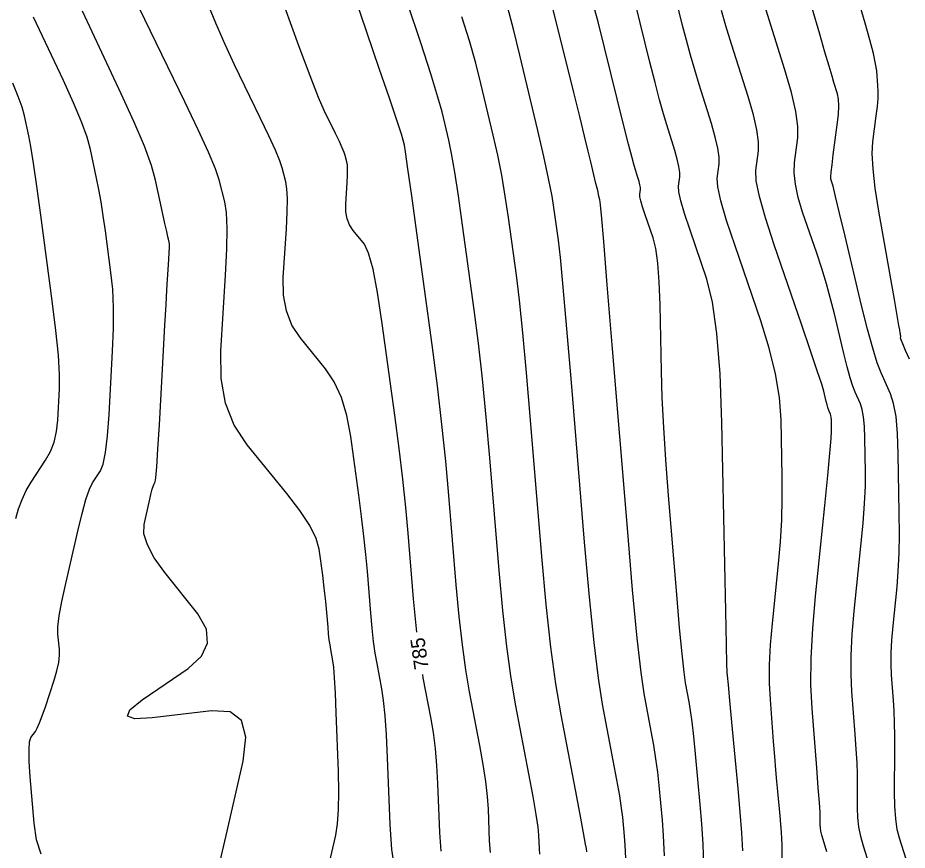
# Model space of a CAD drawing. Extents: x 2082232 to 2083549, y 592624 to 593832.
# Drawn here: x 2082528.23 to 2082571.85, y 593085.62 to 593126.44 of the extents above; entities that cross this region are included whole.
import ezdxf

# ---------------------------------------------------------------- set-up
doc = ezdxf.new("R2010")
doc.units = 0
doc.layers.add('DT_X_Contour_Major', color=7, linetype='Continuous')
doc.layers.add('DT_X_Contour_Minor', color=7, linetype='Continuous')

msp = doc.modelspace()

# ---------------------------------------------------------------- linework, layer by layer
at = {"layer": 'DT_X_Contour_Major'}
for points in [[(2082559.944, 593085.357), (2082559.9, 593086.34), (2082559.845, 593087.094), (2082559.682, 593088.8), (2082559.612, 593089.447), (2082559.525, 593090.106), (2082559.419, 593090.778), (2082559.296, 593091.463), (2082558.943, 593093.306), (2082558.793, 593094.331), (2082558.606, 593096.026), (2082558.383, 593098.389), (2082558.124, 593101.422), (2082557.384, 593110.401), (2082557.14, 593113.354), (2082556.964, 593115.481), (2082556.855, 593116.78), (2082556.813, 593117.253), (2082556.791, 593117.411), (2082556.772, 593117.512), (2082556.732, 593117.699), (2082556.669, 593117.969), (2082556.585, 593118.325), (2082556.332, 593119.385), (2082556.209, 593119.895), (2082556.028, 593120.632), (2082555.792, 593121.595), (2082555.498, 593122.784), (2082554.64, 593126.255), (2082554.344, 593127.414)], [(2082570.117, 593084.525), (2082569.708, 593085.822), (2082569.574, 593086.303), (2082569.479, 593086.772), (2082569.423, 593087.231), (2082569.407, 593087.68), (2082569.414, 593088.861), (2082569.408, 593089.346), (2082569.387, 593089.917), (2082569.349, 593090.572), (2082569.295, 593091.313), (2082569.13, 593093.402), (2082569.091, 593094.237), (2082569.099, 593095.173), (2082569.152, 593096.212), (2082569.251, 593097.353), (2082569.577, 593100.533), (2082569.682, 593101.654), (2082569.755, 593102.633), (2082569.794, 593103.469), (2082569.8, 593104.163), (2082569.773, 593105.824), (2082569.751, 593106.396), (2082569.707, 593106.868), (2082569.642, 593107.238), (2082569.554, 593107.507), (2082569.289, 593108.091), (2082569.181, 593108.374), (2082569.054, 593108.784), (2082568.908, 593109.322), (2082568.743, 593109.987), (2082568.278, 593111.931), (2082568.093, 593112.664), (2082567.887, 593113.403), (2082567.66, 593114.148), (2082567.411, 593114.901), (2082566.719, 593116.916), (2082566.5, 593117.635), (2082566.361, 593118.278), (2082566.302, 593118.846), (2082566.323, 593119.34), (2082566.485, 593120.555), (2082566.491, 593121.106), (2082566.386, 593121.846), (2082566.171, 593122.776), (2082565.845, 593123.896), (2082564.829, 593127.135)], [(2082547.797, 593096.318), (2082547.743, 593096.803), (2082547.639, 593097.948), (2082547.374, 593101.163), (2082547.258, 593102.429), (2082547.11, 593103.816), (2082546.929, 593105.324), (2082546.715, 593106.952), (2082546.101, 593111.457), (2082545.874, 593112.967), (2082545.652, 593114.117), (2082545.437, 593114.909), (2082545.228, 593115.341), (2082544.678, 593116.015), (2082544.5, 593116.286), (2082544.381, 593116.592), (2082544.319, 593116.933), (2082544.315, 593117.31), (2082544.381, 593118.363), (2082544.399, 593118.722), (2082544.404, 593119.011), (2082544.394, 593119.231), (2082544.371, 593119.38), (2082544.291, 593119.683), (2082544.239, 593119.836), (2082544.142, 593120.068), (2082544.001, 593120.377), (2082543.816, 593120.765), (2082543.261, 593121.904), (2082542.984, 593122.541), (2082542.57, 593123.595), (2082542.017, 593125.067), (2082541.327, 593126.957)], [(2082528.135, 593101.887), (2082528.267, 593102.369), (2082528.437, 593102.829), (2082528.645, 593103.266), (2082528.891, 593103.679), (2082529.597, 593104.75), (2082529.833, 593105.173), (2082530.011, 593105.641), (2082530.13, 593106.153), (2082530.192, 593106.709), (2082530.278, 593108.252), (2082530.28, 593108.955), (2082530.221, 593109.907), (2082530.101, 593111.109), (2082529.92, 593112.561), (2082529.357, 593116.764), (2082529.162, 593118.189), (2082529, 593119.312), (2082528.871, 593120.132), (2082528.775, 593120.651), (2082528.564, 593121.631), (2082528.446, 593122.055), (2082528.252, 593122.591), (2082527.982, 593123.241)], [(2082548.998, 593085.579), (2082548.927, 593086.491), (2082548.834, 593088.893), (2082548.786, 593089.771), (2082548.712, 593090.607), (2082548.612, 593091.399), (2082548.486, 593092.147), (2082548.116, 593094.084), (2082548.089, 593094.239)]]:
    msp.add_lwpolyline(points, dxfattribs=at)
at = {"layer": 'DT_X_Contour_Minor'}
for points in [[(2082571.964, 593109.701), (2082571.77, 593110.133), (2082571.632, 593110.45), (2082571.55, 593110.65), (2082571.523, 593110.734), (2082571.527, 593110.805), (2082571.527, 593110.836), (2082571.524, 593110.876), (2082571.517, 593110.925), (2082571.508, 593110.982), (2082571.478, 593111.148), (2082571.442, 593111.354), (2082571.355, 593111.85), (2082571.217, 593112.635), (2082570.46, 593116.962), (2082570.281, 593118.088), (2082570.171, 593119.03), (2082570.131, 593119.786), (2082570.161, 593120.358), (2082570.331, 593121.634), (2082570.384, 593122.087), (2082570.416, 593122.487), (2082570.425, 593122.834), (2082570.413, 593123.129), (2082570.353, 593123.846), (2082570.3, 593124.193), (2082570.188, 593124.699), (2082570.016, 593125.362), (2082569.784, 593126.184), (2082569.086, 593128.585)], [(2082551.414, 593085.506), (2082551.369, 593086.091), (2082551.309, 593087.631), (2082551.266, 593088.26), (2082551.181, 593088.992), (2082551.055, 593089.825), (2082550.887, 593090.761), (2082550.384, 593093.393), (2082550.202, 593094.462), (2082550.033, 593095.693), (2082549.878, 593097.087), (2082549.736, 593098.643), (2082549.376, 593103.01), (2082549.223, 593104.701), (2082549.033, 593106.497), (2082548.807, 593108.399), (2082548.544, 593110.406), (2082547.796, 593115.9), (2082547.547, 593117.714), (2082547.363, 593119.036), (2082547.244, 593119.866), (2082547.19, 593120.203), (2082547.132, 593120.447), (2082547.042, 593120.736), (2082546.817, 593121.418), (2082546.456, 593122.494), (2082545.96, 593123.964), (2082544.456, 593128.41)], [(2082565.716, 593085.235), (2082565.71, 593085.905), (2082565.703, 593086.181), (2082565.685, 593086.507), (2082565.657, 593086.882), (2082565.62, 593087.307), (2082565.505, 593088.505), (2082565.46, 593088.994), (2082565.411, 593089.565), (2082565.357, 593090.216), (2082565.298, 593090.948), (2082565.135, 593093.008), (2082565.096, 593093.821), (2082565.1, 593094.715), (2082565.147, 593095.688), (2082565.238, 593096.743), (2082565.537, 593099.661), (2082565.632, 593100.749), (2082565.694, 593101.826), (2082565.722, 593102.89), (2082565.717, 593103.941), (2082565.658, 593106.73), (2082565.58, 593107.818), (2082565.388, 593108.989), (2082565.084, 593110.245), (2082564.667, 593111.584), (2082563.403, 593115.267), (2082562.992, 593116.509), (2082562.71, 593117.473), (2082562.555, 593118.16), (2082562.527, 593118.568), (2082562.623, 593119.285), (2082562.626, 593119.61), (2082562.564, 593120.047), (2082562.437, 593120.596), (2082562.245, 593121.257), (2082561.645, 593123.169), (2082561.426, 593123.888), (2082561.217, 593124.611), (2082561.02, 593125.339), (2082560.833, 593126.07), (2082560.35, 593128.026)], [(2082571.789, 593085.189), (2082571.466, 593086.215), (2082571.36, 593086.646), (2082571.286, 593087.17), (2082571.243, 593087.786), (2082571.232, 593088.494), (2082571.244, 593090.506), (2082571.243, 593091.226), (2082571.232, 593091.875), (2082571.21, 593092.455), (2082571.178, 593092.964), (2082571.078, 593094.228), (2082571.055, 593094.733), (2082571.059, 593095.3), (2082571.091, 593095.929), (2082571.151, 593096.62), (2082571.348, 593098.544), (2082571.411, 593099.311), (2082571.45, 593100.17), (2082571.467, 593101.121), (2082571.46, 593102.164), (2082571.411, 593105.065), (2082571.374, 593106.066), (2082571.298, 593106.889), (2082571.183, 593107.536), (2082571.029, 593108.007), (2082570.567, 593109.028), (2082570.378, 593109.522), (2082570.155, 593110.238), (2082569.9, 593111.178), (2082569.612, 593112.34), (2082568.8, 593115.737), (2082568.532, 593116.857), (2082568.335, 593117.673), (2082568.21, 593118.183), (2082568.156, 593118.387), (2082568.109, 593118.524), (2082568.103, 593118.638), (2082568.119, 593118.876), (2082568.159, 593119.239), (2082568.221, 593119.725), (2082568.417, 593121.19), (2082568.473, 593121.697), (2082568.494, 593122.119), (2082568.48, 593122.457), (2082568.431, 593122.711), (2082568.254, 593123.275), (2082568.161, 593123.58), (2082568.014, 593124.075), (2082567.814, 593124.759), (2082567.559, 593125.632), (2082566.809, 593128.213)], [(2082543.529, 593085.083), (2082543.821, 593086.365), (2082543.912, 593086.92), (2082543.965, 593087.625), (2082543.98, 593088.478), (2082543.958, 593089.481), (2082543.846, 593092.353), (2082543.805, 593093.322), (2082543.764, 593094.072), (2082543.724, 593094.604), (2082543.685, 593094.919), (2082543.58, 593095.467), (2082543.542, 593095.689), (2082543.507, 593095.945), (2082543.475, 593096.235), (2082543.445, 593096.559), (2082543.37, 593097.468), (2082543.337, 593097.826), (2082543.295, 593098.218), (2082543.244, 593098.644), (2082543.184, 593099.105), (2082543.01, 593100.379), (2082542.862, 593100.908), (2082542.547, 593101.542), (2082542.067, 593102.281), (2082541.42, 593103.123), (2082539.474, 593105.509), (2082538.846, 593106.466), (2082538.423, 593107.549), (2082538.204, 593108.758), (2082538.19, 593110.092), (2082538.424, 593113.817), (2082538.488, 593115.089), (2082538.503, 593116.113), (2082538.47, 593116.889), (2082538.388, 593117.416), (2082538.106, 593118.491), (2082537.921, 593119.032), (2082537.579, 593119.851), (2082537.08, 593120.947), (2082536.422, 593122.32), (2082534.46, 593126.351), (2082533.802, 593127.711)], [(2082546.776, 593084.385), (2082546.581, 593085.652), (2082546.484, 593086.891), (2082546.358, 593090.154), (2082546.306, 593091.283), (2082546.243, 593092.222), (2082546.169, 593092.972), (2082546.085, 593093.533), (2082545.848, 593094.775), (2082545.762, 593095.28), (2082545.682, 593095.861), (2082545.609, 593096.519), (2082545.542, 593097.254), (2082545.372, 593099.315), (2082545.298, 593100.127), (2082545.203, 593101.017), (2082545.087, 593101.984), (2082544.949, 593103.029), (2082544.555, 593105.918), (2082544.368, 593106.937), (2082544.1, 593107.83), (2082543.752, 593108.595), (2082543.324, 593109.232), (2082542.076, 593110.762), (2082541.673, 593111.376), (2082541.402, 593112.07), (2082541.261, 593112.845), (2082541.252, 593113.701), (2082541.403, 593116.09), (2082541.444, 593116.906), (2082541.453, 593117.562), (2082541.432, 593118.06), (2082541.38, 593118.398), (2082541.199, 593119.087), (2082541.08, 593119.434), (2082540.861, 593119.959), (2082540.54, 593120.662), (2082540.119, 593121.543), (2082538.86, 593124.128), (2082538.393, 593125.126), (2082537.936, 593126.181), (2082537.488, 593127.293)], [(2082553.831, 593085.433), (2082553.811, 593085.691), (2082553.785, 593086.37), (2082553.746, 593086.749), (2082553.65, 593087.376), (2082553.498, 593088.252), (2082553.288, 593089.375), (2082552.652, 593092.702), (2082552.421, 593094.053), (2082552.208, 593095.609), (2082552.012, 593097.371), (2082551.833, 593099.338), (2082551.378, 593104.858), (2082551.202, 593106.864), (2082551.016, 593108.743), (2082550.819, 593110.494), (2082550.612, 593112.118), (2082550.044, 593116.278), (2082549.843, 593117.708), (2082549.663, 593118.879), (2082549.505, 593119.79), (2082549.37, 593120.442), (2082549.037, 593121.834), (2082548.837, 593122.558), (2082548.488, 593123.687), (2082547.989, 593125.22), (2082547.34, 593127.158)], [(2082561.881, 593084.869), (2082561.841, 593085.917), (2082561.781, 593086.918), (2082561.702, 593087.871), (2082561.466, 593090.35), (2082561.38, 593091.206), (2082561.3, 593091.917), (2082561.226, 593092.482), (2082561.157, 593092.901), (2082560.98, 593093.825), (2082560.903, 593094.356), (2082560.806, 593095.255), (2082560.687, 593096.523), (2082560.547, 593098.159), (2082560.147, 593103.015), (2082560.013, 593104.761), (2082559.909, 593106.358), (2082559.837, 593107.805), (2082559.796, 593109.104), (2082559.727, 593112.367), (2082559.686, 593113.49), (2082559.616, 593114.413), (2082559.516, 593115.136), (2082559.386, 593115.659), (2082558.999, 593116.786), (2082558.873, 593117.166), (2082558.787, 593117.461), (2082558.739, 593117.671), (2082558.731, 593117.796), (2082558.76, 593118.015), (2082558.761, 593118.115), (2082558.742, 593118.249), (2082558.704, 593118.417), (2082558.645, 593118.619), (2082558.461, 593119.204), (2082558.357, 593119.572), (2082558.183, 593120.24), (2082557.939, 593121.206), (2082557.625, 593122.471), (2082556.693, 593126.242), (2082556.335, 593127.545)], [(2082563.785, 593085.591), (2082563.738, 593086.477), (2082563.663, 593087.496), (2082563.56, 593088.648), (2082563.25, 593091.899), (2082563.149, 593092.966), (2082563.076, 593093.728), (2082563.032, 593094.186), (2082563.017, 593094.34), (2082563.016, 593094.345), (2082563.016, 593094.347), (2082563.016, 593094.351), (2082563.015, 593094.358), (2082563.012, 593094.389), (2082563.005, 593094.723), (2082562.984, 593095.708), (2082562.949, 593097.344), (2082562.901, 593099.63), (2082562.755, 593106.594), (2082562.668, 593108.992), (2082562.518, 593110.963), (2082562.304, 593112.506), (2082562.026, 593113.621), (2082561.201, 593116.027), (2082560.933, 593116.838), (2082560.748, 593117.467), (2082560.647, 593117.915), (2082560.629, 593118.182), (2082560.692, 593118.65), (2082560.694, 593118.863), (2082560.653, 593119.148), (2082560.57, 593119.506), (2082560.445, 593119.938), (2082560.053, 593121.186), (2082559.891, 593121.73), (2082559.7, 593122.426), (2082559.479, 593123.272), (2082559.229, 593124.27), (2082558.521, 593127.134)], [(2082538.15, 593085.095), (2082538.448, 593086.342), (2082539.282, 593089.992), (2082539.419, 593091.174), (2082539.206, 593091.979), (2082538.642, 593092.41), (2082537.728, 593092.466), (2082534.824, 593092.114), (2082533.977, 593092.07), (2082533.612, 593092.203), (2082533.73, 593092.513), (2082534.331, 593093), (2082536.579, 593094.534), (2082537.24, 593095.133), (2082537.54, 593095.779), (2082537.479, 593096.471), (2082537.055, 593097.211), (2082535.443, 593099.247), (2082534.925, 593099.966), (2082534.583, 593100.598), (2082534.415, 593101.142), (2082534.422, 593101.598), (2082534.674, 593102.698), (2082534.76, 593103.064), (2082534.828, 593103.335), (2082534.878, 593103.512), (2082534.91, 593103.595), (2082534.973, 593103.69), (2082535.003, 593103.892), (2082535.047, 593104.426), (2082535.103, 593105.292), (2082535.173, 593106.49), (2082535.376, 593110.129), (2082535.446, 593111.369), (2082535.502, 593112.362), (2082535.545, 593113.106), (2082535.575, 593113.602), (2082535.638, 593114.595), (2082535.656, 593114.927), (2082535.666, 593115.179), (2082535.666, 593115.351), (2082535.657, 593115.444), (2082535.621, 593115.582), (2082535.593, 593115.703), (2082535.535, 593115.96), (2082535.449, 593116.355), (2082535.334, 593116.887), (2082534.988, 593118.488), (2082534.785, 593119.203), (2082534.437, 593120.147), (2082533.943, 593121.32), (2082533.303, 593122.722), (2082531.403, 593126.768)], [(2082558.043, 593085.233), (2082558.018, 593085.87), (2082557.987, 593086.316), (2082557.898, 593087.251), (2082557.844, 593087.688), (2082557.749, 593088.295), (2082557.613, 593089.074), (2082557.435, 593090.024), (2082556.907, 593092.786), (2082556.703, 593094.059), (2082556.489, 593095.807), (2082556.264, 593098.03), (2082556.027, 593100.727), (2082555.382, 593108.553), (2082555.161, 593111.191), (2082554.981, 593113.235), (2082554.843, 593114.685), (2082554.746, 593115.541), (2082554.542, 593117.033), (2082554.434, 593117.696), (2082554.263, 593118.564), (2082554.028, 593119.638), (2082553.729, 593120.918), (2082552.847, 593124.607), (2082552.537, 593125.881), (2082552.265, 593126.936)], [(2082567.913, 593085.546), (2082567.723, 593086.15), (2082567.66, 593086.365), (2082567.616, 593086.556), (2082567.59, 593086.722), (2082567.581, 593086.865), (2082567.583, 593087.215), (2082567.573, 593087.466), (2082567.541, 593087.958), (2082567.488, 593088.69), (2082567.412, 593089.662), (2082567.182, 593092.576), (2082567.128, 593093.74), (2082567.138, 593095.046), (2082567.212, 593096.496), (2082567.351, 593098.087), (2082567.805, 593102.522), (2082567.954, 593103.996), (2082568.059, 593105.095), (2082568.122, 593105.817), (2082568.141, 593106.162), (2082568.134, 593106.582), (2082568.128, 593106.727), (2082568.117, 593106.846), (2082568.101, 593106.94), (2082568.078, 593107.008), (2082568.012, 593107.155), (2082567.984, 593107.227), (2082567.952, 593107.331), (2082567.915, 593107.466), (2082567.873, 593107.635), (2082567.756, 593108.126), (2082567.655, 593108.47), (2082567.439, 593109.133), (2082567.11, 593110.114), (2082566.666, 593111.415), (2082565.33, 593115.309), (2082564.897, 593116.631), (2082564.603, 593117.68), (2082564.445, 593118.454), (2082564.425, 593118.954), (2082564.554, 593119.92), (2082564.559, 593120.358), (2082564.475, 593120.947), (2082564.304, 593121.686), (2082564.045, 593122.577), (2082563.237, 593125.152), (2082562.96, 593126.046), (2082562.734, 593126.797)], [(2082529.382, 593085.427), (2082529.154, 593086.137), (2082529.031, 593086.943), (2082528.845, 593089.217), (2082528.795, 593089.977), (2082528.782, 593090.553), (2082528.808, 593090.943), (2082528.872, 593091.149), (2082529.095, 593091.452), (2082529.188, 593091.612), (2082529.3, 593091.867), (2082529.432, 593092.215), (2082529.584, 593092.657), (2082530.014, 593093.961), (2082530.151, 593094.423), (2082530.241, 593094.832), (2082530.283, 593095.187), (2082530.277, 593095.488), (2082530.199, 593096.222), (2082530.201, 593096.583), (2082530.265, 593097.116), (2082530.392, 593097.822), (2082530.582, 593098.7), (2082531.171, 593101.271), (2082531.382, 593102.142), (2082531.574, 593102.827), (2082531.747, 593103.325), (2082531.901, 593103.637), (2082532.285, 593104.22), (2082532.42, 593104.557), (2082532.534, 593105.13), (2082532.629, 593105.939), (2082532.704, 593106.985), (2082532.877, 593110.09), (2082532.921, 593111.204), (2082532.923, 593112.22), (2082532.883, 593113.136), (2082532.801, 593113.953), (2082532.527, 593116), (2082532.423, 593116.737), (2082532.316, 593117.413), (2082532.207, 593118.028), (2082532.095, 593118.583), (2082531.793, 593119.979), (2082531.625, 593120.584), (2082531.349, 593121.349), (2082530.963, 593122.276), (2082530.469, 593123.363), (2082529.006, 593126.478)], [(2082556.13, 593085.539), (2082556.114, 593085.702), (2082556.076, 593085.928), (2082555.973, 593086.484), (2082555.806, 593087.37), (2082555.575, 593088.585), (2082554.871, 593092.267), (2082554.614, 593093.787), (2082554.371, 593095.589), (2082554.144, 593097.67), (2082553.93, 593100.032), (2082553.38, 593106.706), (2082553.182, 593109.028), (2082552.999, 593110.989), (2082552.831, 593112.59), (2082552.679, 593113.83), (2082552.293, 593116.656), (2082552.139, 593117.702), (2082551.963, 593118.721), (2082551.767, 593119.714), (2082551.549, 593120.68), (2082550.942, 593123.22), (2082550.687, 593124.219), (2082550.377, 593125.312), (2082550.011, 593126.497)]]:
    msp.add_lwpolyline(points, dxfattribs=at)

# ---------------------------------------------------------------- texts
at = {"layer": 'DT_X_Contour_Major'}
msp.add_text('785', height=0.7, rotation=97.9934, dxfattribs=at).set_placement((2082548.383, 593094.542))

doc.saveas('drawing.dxf')
